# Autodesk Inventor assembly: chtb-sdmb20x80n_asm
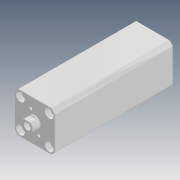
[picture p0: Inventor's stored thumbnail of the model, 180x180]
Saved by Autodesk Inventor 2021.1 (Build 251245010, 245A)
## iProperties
Company: Microsoft
Created: 2018-05
Part Number: chtb-sdmb20x80n_asm
Description: STEP AP214
Document SubType Name: Assembly
Designer: user
Title: chtb-sdmb20x80n_asm.STEP
Author: Windows
Revision Number: ÈÎºÎ
Sending System: SolidWorks 2015
Preprocessor: SwSTEP 2.0
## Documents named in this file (4)
- D:\Vault_2016\Projekty\Clamptek\Hydraulic\CHTB\CHTB-20\Inventor\CHTB-SDMB20x80N\chtb-sdmb20x80n_asm.iam
- D:\Vault_2016\Projekty\Clamptek\Hydraulic\CHTB\CHTB-20\Inventor\CHTB-SDMB20x80N\CHTB-SDMB20X80NBT.ipt
- D:\Vault_2016\Projekty\Clamptek\Hydraulic\CHTB\CHTB-20\Inventor\CHTB-SDMB20x80N\CHTB-SDMB20X80NHSG.ipt
- D:\Vault_2016\Projekty\Clamptek\Hydraulic\CHTB\CHTB-20\Inventor\CHTB-SDMB20x80N\QG_3.ipt
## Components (3 placed, 3 different names)
1. CHTB-SDMB20X80NBT_1
2. CHTB-SDMB20X80NHSG_2
3. QG_3_3
